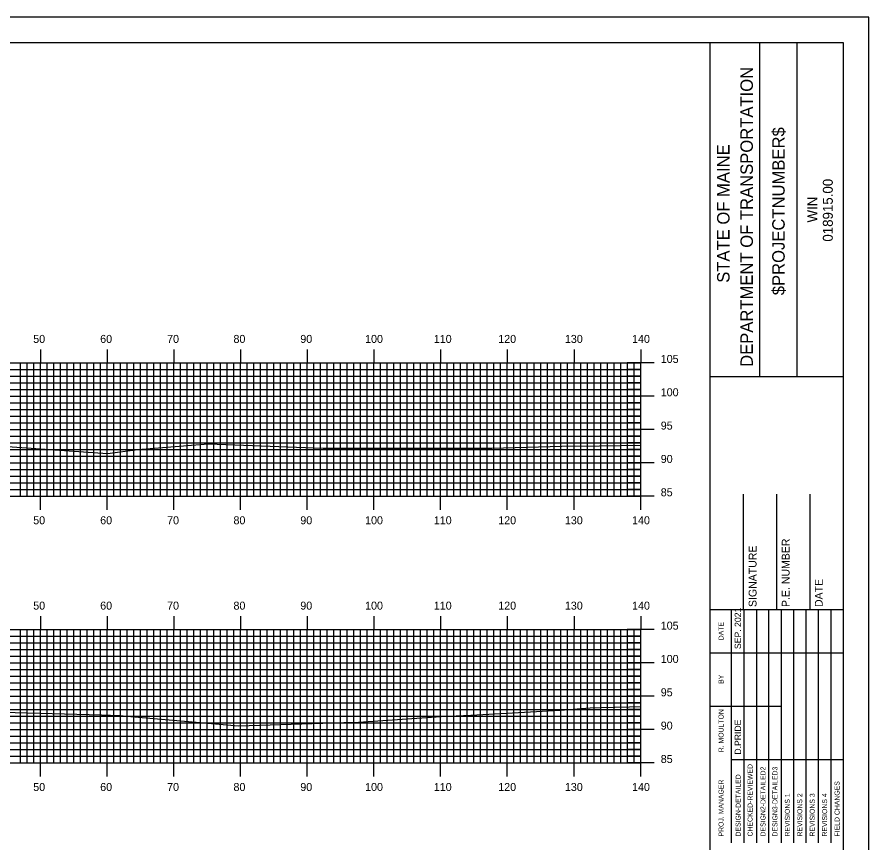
# Model space of a CAD drawing. Extents: x 1763759 to 1764102, y 442591 to 442811.
# Drawn here: x 1763970.8 to 1764098.5, y 442686.7 to 442810.5 of the extents above; entities that cross this region are included whole.
import ezdxf

# ---------------------------------------------------------------- set-up
doc = ezdxf.new("R2010")
doc.units = 0
for name, color, linetype in [('BORDER', 7, 'Continuous'), ('H_V ANNOTATION', 7, 'Continuous'), ('MAJOR', 7, 'Continuous'), ('MINOR', 7, 'Continuous'), ('PLOT BOUNDARY', 7, 'Continuous'), ('S_Roadway_Centerline', 7, 'Continuous')]:
    doc.layers.add(name, color=color, linetype=linetype)

msp = doc.modelspace()

# ---------------------------------------------------------------- linework, layer by layer
at = {"layer": 'BORDER'}
for p, q in [((1764074.72, 442596.67), (1764074.72, 442806.67)), ((1764082.18, 442756.66), (1764082.18, 442806.66)), ((1764087.77, 442756.66), (1764087.77, 442806.66)), ((1764074.72, 442756.65), (1764094.72, 442756.65)), ((1764079.72, 442721.67), (1764079.72, 442738.97)), ((1764084.72, 442721.67), (1764084.72, 442738.97)), ((1764089.72, 442721.67), (1764089.72, 442738.97)), ((1764074.72, 442721.67), (1764094.72, 442721.67))]:
    msp.add_line(p, q, dxfattribs=at)
msp.add_lwpolyline([(1763774.72, 442596.67), (1764094.72, 442596.67), (1764094.72, 442806.67), (1763774.72, 442806.67)], close=True, dxfattribs=at)
for points in [[(1764077.95, 442715.17), (1764077.95, 442721.67)], [(1764079.81, 442686.68), (1764079.81, 442721.67)], [(1764081.68, 442721.67), (1764081.68, 442686.68)], [(1764083.54, 442686.68), (1764083.54, 442721.67)], [(1764085.4, 442686.68), (1764085.4, 442721.67)], [(1764087.27, 442686.68), (1764087.27, 442721.67)], [(1764089.13, 442686.68), (1764089.13, 442721.67)], [(1764090.99, 442686.68), (1764090.99, 442721.67)], [(1764092.86, 442686.68), (1764092.86, 442721.67)], [(1764077.95, 442686.68), (1764077.95, 442720.26)], [(1764074.72, 442715.17), (1764094.72, 442715.17)], [(1764074.72, 442707.17), (1764077.95, 442707.17)], [(1764077.95, 442707.17), (1764085.4, 442707.17)], [(1764077.95, 442699.17), (1764094.72, 442699.17)]]:
    msp.add_lwpolyline(points, dxfattribs=at)
at = {"layer": 'MAJOR'}
for p, q in [((1763974.32, 442760.67), (1763974.32, 442758.67)), ((1763984.32, 442760.67), (1763984.32, 442758.67)), ((1763994.32, 442760.67), (1763994.32, 442758.67)), ((1764004.32, 442760.67), (1764004.32, 442758.67)), ((1764014.32, 442760.67), (1764014.32, 442758.67)), ((1764024.32, 442760.67), (1764024.32, 442758.67)), ((1764034.32, 442760.67), (1764034.32, 442758.67)), ((1764044.32, 442760.67), (1764044.32, 442758.67)), ((1764054.32, 442760.67), (1764054.32, 442758.67)), ((1764064.32, 442760.67), (1764064.32, 442758.67)), ((1763784.32, 442758.67), (1764064.32, 442758.67)), ((1763784.32, 442758.67), (1764064.32, 442758.67)), ((1763974.32, 442738.67), (1763974.32, 442758.67)), ((1763984.32, 442738.67), (1763984.32, 442758.67)), ((1763994.32, 442738.67), (1763994.32, 442758.67)), ((1764004.32, 442738.67), (1764004.32, 442758.67)), ((1764014.32, 442738.67), (1764014.32, 442758.67)), ((1764024.32, 442738.67), (1764024.32, 442758.67)), ((1764034.32, 442738.67), (1764034.32, 442758.67)), ((1764044.32, 442738.67), (1764044.32, 442758.67)), ((1764054.32, 442738.67), (1764054.32, 442758.67)), ((1764066.32, 442758.67), (1764062.31, 442758.67)), ((1764064.32, 442738.67), (1764064.32, 442758.67)), ((1764064.32, 442738.67), (1764064.32, 442758.67)), ((1763784.32, 442753.67), (1764064.32, 442753.67)), ((1764066.32, 442753.67), (1764062.31, 442753.67)), ((1763784.32, 442748.67), (1764064.32, 442748.67)), ((1764066.32, 442748.67), (1764062.31, 442748.67)), ((1763784.32, 442743.67), (1764064.32, 442743.67)), ((1764066.32, 442743.67), (1764062.31, 442743.67)), ((1763784.32, 442738.67), (1764064.32, 442738.67)), ((1763784.32, 442738.67), (1764064.32, 442738.67)), ((1763974.32, 442736.66), (1763974.32, 442738.67)), ((1763984.32, 442736.66), (1763984.32, 442738.67)), ((1763994.32, 442736.66), (1763994.32, 442738.67)), ((1764004.32, 442736.66), (1764004.32, 442738.67)), ((1764014.32, 442736.66), (1764014.32, 442738.67)), ((1764024.32, 442736.66), (1764024.32, 442738.67)), ((1764034.32, 442736.66), (1764034.32, 442738.67)), ((1764044.32, 442736.66), (1764044.32, 442738.67)), ((1764054.32, 442736.66), (1764054.32, 442738.67)), ((1764066.32, 442738.67), (1764062.31, 442738.67)), ((1764064.32, 442736.66), (1764064.32, 442738.67)), ((1763974.32, 442720.67), (1763974.32, 442718.67)), ((1763984.32, 442720.67), (1763984.32, 442718.67)), ((1763994.32, 442720.67), (1763994.32, 442718.67)), ((1764004.32, 442720.67), (1764004.32, 442718.67)), ((1764014.32, 442720.67), (1764014.32, 442718.67)), ((1764024.32, 442720.67), (1764024.32, 442718.67)), ((1764034.32, 442720.67), (1764034.32, 442718.67)), ((1764044.32, 442720.67), (1764044.32, 442718.67)), ((1764054.32, 442720.67), (1764054.32, 442718.67)), ((1764064.32, 442720.67), (1764064.32, 442718.67)), ((1763784.32, 442718.67), (1764064.32, 442718.67)), ((1763784.32, 442718.67), (1764064.32, 442718.67)), ((1763974.32, 442698.67), (1763974.32, 442718.67)), ((1763984.32, 442698.67), (1763984.32, 442718.67)), ((1763994.32, 442698.67), (1763994.32, 442718.67)), ((1764004.32, 442698.67), (1764004.32, 442718.67)), ((1764014.32, 442698.67), (1764014.32, 442718.67)), ((1764024.32, 442698.67), (1764024.32, 442718.67)), ((1764034.32, 442698.67), (1764034.32, 442718.67)), ((1764044.32, 442698.67), (1764044.32, 442718.67)), ((1764054.32, 442698.67), (1764054.32, 442718.67)), ((1764066.32, 442718.67), (1764062.31, 442718.67)), ((1764064.32, 442698.67), (1764064.32, 442718.67)), ((1764064.32, 442698.67), (1764064.32, 442718.67)), ((1763784.32, 442713.67), (1764064.32, 442713.67)), ((1764066.32, 442713.67), (1764062.31, 442713.67)), ((1763784.32, 442708.67), (1764064.32, 442708.67)), ((1764066.32, 442708.67), (1764062.31, 442708.67)), ((1763784.32, 442703.67), (1764064.32, 442703.67)), ((1764066.32, 442703.67), (1764062.31, 442703.67)), ((1763784.32, 442698.67), (1764064.32, 442698.67)), ((1763784.32, 442698.67), (1764064.32, 442698.67)), ((1763974.32, 442696.66), (1763974.32, 442698.67)), ((1763984.32, 442696.66), (1763984.32, 442698.67)), ((1763994.32, 442696.66), (1763994.32, 442698.67)), ((1764004.32, 442696.66), (1764004.32, 442698.67)), ((1764014.32, 442696.66), (1764014.32, 442698.67)), ((1764024.32, 442696.66), (1764024.32, 442698.67)), ((1764034.32, 442696.66), (1764034.32, 442698.67)), ((1764044.32, 442696.66), (1764044.32, 442698.67)), ((1764054.32, 442696.66), (1764054.32, 442698.67)), ((1764066.32, 442698.67), (1764062.31, 442698.67)), ((1764064.32, 442696.66), (1764064.32, 442698.67))]:
    msp.add_line(p, q, dxfattribs=at)
at = {"layer": 'MINOR'}
for p, q in [((1763971.32, 442738.67), (1763971.32, 442758.67)), ((1763972.32, 442738.67), (1763972.32, 442758.67)), ((1763973.32, 442738.67), (1763973.32, 442758.67)), ((1763975.32, 442738.67), (1763975.32, 442758.67)), ((1763976.32, 442738.67), (1763976.32, 442758.67)), ((1763977.32, 442738.67), (1763977.32, 442758.67)), ((1763978.32, 442738.67), (1763978.32, 442758.67)), ((1763979.32, 442738.67), (1763979.32, 442758.67)), ((1763980.32, 442738.67), (1763980.32, 442758.67)), ((1763981.32, 442738.67), (1763981.32, 442758.67)), ((1763982.32, 442738.67), (1763982.32, 442758.67)), ((1763983.32, 442738.67), (1763983.32, 442758.67)), ((1763985.32, 442738.67), (1763985.32, 442758.67)), ((1763986.32, 442738.67), (1763986.32, 442758.67)), ((1763987.32, 442738.67), (1763987.32, 442758.67)), ((1763988.32, 442738.67), (1763988.32, 442758.67)), ((1763989.32, 442738.67), (1763989.32, 442758.67)), ((1763990.32, 442738.67), (1763990.32, 442758.67)), ((1763991.32, 442738.67), (1763991.32, 442758.67)), ((1763992.32, 442738.67), (1763992.32, 442758.67)), ((1763993.32, 442738.67), (1763993.32, 442758.67)), ((1763995.32, 442738.67), (1763995.32, 442758.67)), ((1763996.32, 442738.67), (1763996.32, 442758.67)), ((1763997.32, 442738.67), (1763997.32, 442758.67)), ((1763998.32, 442738.67), (1763998.32, 442758.67)), ((1763999.32, 442738.67), (1763999.32, 442758.67)), ((1764000.32, 442738.67), (1764000.32, 442758.67)), ((1764001.32, 442738.67), (1764001.32, 442758.67)), ((1764002.32, 442738.67), (1764002.32, 442758.67)), ((1764003.32, 442738.67), (1764003.32, 442758.67)), ((1764005.32, 442738.67), (1764005.32, 442758.67)), ((1764006.32, 442738.67), (1764006.32, 442758.67)), ((1764007.32, 442738.67), (1764007.32, 442758.67)), ((1764008.32, 442738.67), (1764008.32, 442758.67)), ((1764009.32, 442738.67), (1764009.32, 442758.67)), ((1764010.32, 442738.67), (1764010.32, 442758.67)), ((1764011.32, 442738.67), (1764011.32, 442758.67)), ((1764012.32, 442738.67), (1764012.32, 442758.67)), ((1764013.32, 442738.67), (1764013.32, 442758.67)), ((1764015.32, 442738.67), (1764015.32, 442758.67)), ((1764016.32, 442738.67), (1764016.32, 442758.67)), ((1764017.32, 442738.67), (1764017.32, 442758.67)), ((1764018.32, 442738.67), (1764018.32, 442758.67)), ((1764019.32, 442738.67), (1764019.32, 442758.67)), ((1764020.32, 442738.67), (1764020.32, 442758.67)), ((1764021.32, 442738.67), (1764021.32, 442758.67)), ((1764022.32, 442738.67), (1764022.32, 442758.67)), ((1764023.32, 442738.67), (1764023.32, 442758.67)), ((1764025.32, 442738.67), (1764025.32, 442758.67)), ((1764026.32, 442738.67), (1764026.32, 442758.67)), ((1764027.32, 442738.67), (1764027.32, 442758.67)), ((1764028.32, 442738.67), (1764028.32, 442758.67)), ((1764029.32, 442738.67), (1764029.32, 442758.67)), ((1764030.32, 442738.67), (1764030.32, 442758.67)), ((1764031.32, 442738.67), (1764031.32, 442758.67)), ((1764032.32, 442738.67), (1764032.32, 442758.67)), ((1764033.32, 442738.67), (1764033.32, 442758.67)), ((1764035.32, 442738.67), (1764035.32, 442758.67)), ((1764036.32, 442738.67), (1764036.32, 442758.67)), ((1764037.32, 442738.67), (1764037.32, 442758.67)), ((1764038.32, 442738.67), (1764038.32, 442758.67)), ((1764039.32, 442738.67), (1764039.32, 442758.67)), ((1764040.32, 442738.67), (1764040.32, 442758.67)), ((1764041.32, 442738.67), (1764041.32, 442758.67)), ((1764042.32, 442738.67), (1764042.32, 442758.67)), ((1764043.32, 442738.67), (1764043.32, 442758.67)), ((1764045.32, 442738.67), (1764045.32, 442758.67)), ((1764046.32, 442738.67), (1764046.32, 442758.67)), ((1764047.32, 442738.67), (1764047.32, 442758.67)), ((1764048.32, 442738.67), (1764048.32, 442758.67)), ((1764049.32, 442738.67), (1764049.32, 442758.67)), ((1764050.32, 442738.67), (1764050.32, 442758.67)), ((1764051.32, 442738.67), (1764051.32, 442758.67)), ((1764052.32, 442738.67), (1764052.32, 442758.67)), ((1764053.32, 442738.67), (1764053.32, 442758.67)), ((1764055.32, 442738.67), (1764055.32, 442758.67)), ((1764056.32, 442738.67), (1764056.32, 442758.67)), ((1764057.32, 442738.67), (1764057.32, 442758.67)), ((1764058.32, 442738.67), (1764058.32, 442758.67)), ((1764059.32, 442738.67), (1764059.32, 442758.67)), ((1764060.32, 442738.67), (1764060.32, 442758.67)), ((1764061.32, 442738.67), (1764061.32, 442758.67)), ((1764062.32, 442738.67), (1764062.32, 442758.67)), ((1764063.32, 442738.67), (1764063.32, 442758.67)), ((1763784.32, 442757.67), (1764064.32, 442757.67)), ((1764064.32, 442757.67), (1764062.31, 442757.67)), ((1763784.32, 442756.67), (1764064.32, 442756.67)), ((1764064.32, 442756.67), (1764062.31, 442756.67)), ((1763784.32, 442755.67), (1764064.32, 442755.67)), ((1763784.32, 442754.67), (1764064.32, 442754.67)), ((1764064.32, 442755.67), (1764062.31, 442755.67)), ((1764064.32, 442754.67), (1764062.31, 442754.67)), ((1763784.32, 442752.67), (1764064.32, 442752.67)), ((1764064.32, 442752.67), (1764062.31, 442752.67)), ((1763784.32, 442751.67), (1764064.32, 442751.67)), ((1764064.32, 442751.67), (1764062.31, 442751.67)), ((1763784.32, 442750.67), (1764064.32, 442750.67)), ((1763784.32, 442749.67), (1764064.32, 442749.67)), ((1764064.32, 442750.67), (1764062.31, 442750.67)), ((1764064.32, 442749.67), (1764062.31, 442749.67)), ((1763784.32, 442747.67), (1764064.32, 442747.67)), ((1764064.32, 442747.67), (1764062.31, 442747.67)), ((1763784.32, 442746.67), (1764064.32, 442746.67)), ((1764064.32, 442746.67), (1764062.31, 442746.67)), ((1763784.32, 442745.67), (1764064.32, 442745.67)), ((1763784.32, 442744.67), (1764064.32, 442744.67)), ((1764064.32, 442745.67), (1764062.31, 442745.67)), ((1764064.32, 442744.67), (1764062.31, 442744.67)), ((1763784.32, 442742.67), (1764064.32, 442742.67)), ((1764064.32, 442742.67), (1764062.31, 442742.67)), ((1763784.32, 442741.67), (1764064.32, 442741.67)), ((1763784.32, 442740.67), (1764064.32, 442740.67)), ((1764064.32, 442741.67), (1764062.31, 442741.67)), ((1764064.32, 442740.67), (1764062.31, 442740.67)), ((1763784.32, 442739.67), (1764064.32, 442739.67)), ((1764064.32, 442739.67), (1764062.31, 442739.67)), ((1763784.32, 442717.67), (1764064.32, 442717.67)), ((1763971.32, 442698.67), (1763971.32, 442718.67)), ((1763972.32, 442698.67), (1763972.32, 442718.67)), ((1763973.32, 442698.67), (1763973.32, 442718.67)), ((1763975.32, 442698.67), (1763975.32, 442718.67)), ((1763976.32, 442698.67), (1763976.32, 442718.67)), ((1763977.32, 442698.67), (1763977.32, 442718.67)), ((1763978.32, 442698.67), (1763978.32, 442718.67)), ((1763979.32, 442698.67), (1763979.32, 442718.67)), ((1763980.32, 442698.67), (1763980.32, 442718.67)), ((1763981.32, 442698.67), (1763981.32, 442718.67)), ((1763982.32, 442698.67), (1763982.32, 442718.67)), ((1763983.32, 442698.67), (1763983.32, 442718.67)), ((1763985.32, 442698.67), (1763985.32, 442718.67)), ((1763986.32, 442698.67), (1763986.32, 442718.67)), ((1763987.32, 442698.67), (1763987.32, 442718.67)), ((1763988.32, 442698.67), (1763988.32, 442718.67)), ((1763989.32, 442698.67), (1763989.32, 442718.67)), ((1763990.32, 442698.67), (1763990.32, 442718.67)), ((1763991.32, 442698.67), (1763991.32, 442718.67)), ((1763992.32, 442698.67), (1763992.32, 442718.67)), ((1763993.32, 442698.67), (1763993.32, 442718.67)), ((1763995.32, 442698.67), (1763995.32, 442718.67)), ((1763996.32, 442698.67), (1763996.32, 442718.67)), ((1763997.32, 442698.67), (1763997.32, 442718.67)), ((1763998.32, 442698.67), (1763998.32, 442718.67)), ((1763999.32, 442698.67), (1763999.32, 442718.67)), ((1764000.32, 442698.67), (1764000.32, 442718.67)), ((1764001.32, 442698.67), (1764001.32, 442718.67)), ((1764002.32, 442698.67), (1764002.32, 442718.67)), ((1764003.32, 442698.67), (1764003.32, 442718.67)), ((1764005.32, 442698.67), (1764005.32, 442718.67)), ((1764006.32, 442698.67), (1764006.32, 442718.67)), ((1764007.32, 442698.67), (1764007.32, 442718.67)), ((1764008.32, 442698.67), (1764008.32, 442718.67)), ((1764009.32, 442698.67), (1764009.32, 442718.67)), ((1764010.32, 442698.67), (1764010.32, 442718.67)), ((1764011.32, 442698.67), (1764011.32, 442718.67)), ((1764012.32, 442698.67), (1764012.32, 442718.67)), ((1764013.32, 442698.67), (1764013.32, 442718.67)), ((1764015.32, 442698.67), (1764015.32, 442718.67)), ((1764016.32, 442698.67), (1764016.32, 442718.67)), ((1764017.32, 442698.67), (1764017.32, 442718.67)), ((1764018.32, 442698.67), (1764018.32, 442718.67)), ((1764019.32, 442698.67), (1764019.32, 442718.67)), ((1764020.32, 442698.67), (1764020.32, 442718.67)), ((1764021.32, 442698.67), (1764021.32, 442718.67)), ((1764022.32, 442698.67), (1764022.32, 442718.67)), ((1764023.32, 442698.67), (1764023.32, 442718.67)), ((1764025.32, 442698.67), (1764025.32, 442718.67)), ((1764026.32, 442698.67), (1764026.32, 442718.67)), ((1764027.32, 442698.67), (1764027.32, 442718.67)), ((1764028.32, 442698.67), (1764028.32, 442718.67)), ((1764029.32, 442698.67), (1764029.32, 442718.67)), ((1764030.32, 442698.67), (1764030.32, 442718.67)), ((1764031.32, 442698.67), (1764031.32, 442718.67)), ((1764032.32, 442698.67), (1764032.32, 442718.67)), ((1764033.32, 442698.67), (1764033.32, 442718.67)), ((1764035.32, 442698.67), (1764035.32, 442718.67)), ((1764036.32, 442698.67), (1764036.32, 442718.67)), ((1764037.32, 442698.67), (1764037.32, 442718.67)), ((1764038.32, 442698.67), (1764038.32, 442718.67)), ((1764039.32, 442698.67), (1764039.32, 442718.67)), ((1764040.32, 442698.67), (1764040.32, 442718.67)), ((1764041.32, 442698.67), (1764041.32, 442718.67)), ((1764042.32, 442698.67), (1764042.32, 442718.67)), ((1764043.32, 442698.67), (1764043.32, 442718.67)), ((1764045.32, 442698.67), (1764045.32, 442718.67)), ((1764046.32, 442698.67), (1764046.32, 442718.67)), ((1764047.32, 442698.67), (1764047.32, 442718.67)), ((1764048.32, 442698.67), (1764048.32, 442718.67)), ((1764049.32, 442698.67), (1764049.32, 442718.67)), ((1764050.32, 442698.67), (1764050.32, 442718.67)), ((1764051.32, 442698.67), (1764051.32, 442718.67)), ((1764052.32, 442698.67), (1764052.32, 442718.67)), ((1764053.32, 442698.67), (1764053.32, 442718.67)), ((1764055.32, 442698.67), (1764055.32, 442718.67)), ((1764056.32, 442698.67), (1764056.32, 442718.67)), ((1764057.32, 442698.67), (1764057.32, 442718.67)), ((1764058.32, 442698.67), (1764058.32, 442718.67)), ((1764059.32, 442698.67), (1764059.32, 442718.67)), ((1764060.32, 442698.67), (1764060.32, 442718.67)), ((1764061.32, 442698.67), (1764061.32, 442718.67)), ((1764064.32, 442717.67), (1764062.31, 442717.67)), ((1764062.32, 442698.67), (1764062.32, 442718.67)), ((1764063.32, 442698.67), (1764063.32, 442718.67)), ((1763784.32, 442716.67), (1764064.32, 442716.67)), ((1764064.32, 442716.67), (1764062.31, 442716.67)), ((1763784.32, 442715.67), (1764064.32, 442715.67)), ((1764064.32, 442715.67), (1764062.31, 442715.67)), ((1763784.32, 442714.67), (1764064.32, 442714.67)), ((1764064.32, 442714.67), (1764062.31, 442714.67)), ((1763784.32, 442712.67), (1764064.32, 442712.67)), ((1764064.32, 442712.67), (1764062.31, 442712.67)), ((1763784.32, 442711.67), (1764064.32, 442711.67)), ((1764064.32, 442711.67), (1764062.31, 442711.67)), ((1763784.32, 442710.67), (1764064.32, 442710.67)), ((1764064.32, 442710.67), (1764062.31, 442710.67)), ((1763784.32, 442709.67), (1764064.32, 442709.67)), ((1764064.32, 442709.67), (1764062.31, 442709.67)), ((1763784.32, 442707.67), (1764064.32, 442707.67)), ((1764064.32, 442707.67), (1764062.31, 442707.67)), ((1763784.32, 442706.67), (1764064.32, 442706.67)), ((1764064.32, 442706.67), (1764062.31, 442706.67)), ((1763784.32, 442705.67), (1764064.32, 442705.67)), ((1764064.32, 442705.67), (1764062.31, 442705.67)), ((1763784.32, 442704.67), (1764064.32, 442704.67)), ((1764064.32, 442704.67), (1764062.31, 442704.67)), ((1763784.32, 442702.67), (1764064.32, 442702.67)), ((1764064.32, 442702.67), (1764062.31, 442702.67)), ((1763784.32, 442701.67), (1764064.32, 442701.67)), ((1764064.32, 442701.67), (1764062.31, 442701.67)), ((1763784.32, 442700.67), (1764064.32, 442700.67)), ((1764064.32, 442700.67), (1764062.31, 442700.67)), ((1763784.32, 442699.67), (1764064.32, 442699.67)), ((1764064.32, 442699.67), (1764062.31, 442699.67))]:
    msp.add_line(p, q, dxfattribs=at)
at = {"layer": 'PLOT BOUNDARY'}
msp.add_lwpolyline([(1763758.53, 442590.55), (1764098.53, 442590.55), (1764098.53, 442810.55), (1763758.53, 442810.55)], close=True, dxfattribs=at)
at = {"layer": 'S_Roadway_Centerline'}
for points in [[(1763967.27, 442746.28), (1763975.06, 442745.73), (1763984.41, 442745.09), (1763988.91, 442745.67), (1763999.48, 442746.56), (1764016.71, 442745.91), (1764017.03, 442745.9), (1764017.3, 442745.91), (1764034.83, 442745.87), (1764042.01, 442745.91), (1764052.51, 442746.2), (1764058.13, 442746.24), (1764064.32, 442746.32)], [(1763966.79, 442706.36), (1763983.49, 442705.89), (1763986.17, 442705.81), (1763990.72, 442705.4), (1764004.01, 442704.22), (1764019.79, 442704.72), (1764020.94, 442704.75), (1764021.23, 442704.76), (1764022.03, 442704.79), (1764034.42, 442705.63), (1764038.84, 442705.86), (1764052.23, 442706.61), (1764056.76, 442706.93), (1764058.26, 442706.99), (1764062.64, 442707.08), (1764064.32, 442707.12)]]:
    msp.add_lwpolyline(points, dxfattribs=at)

# ---------------------------------------------------------------- texts
at = {"layer": 'BORDER'}
for s, height, p in [('DEPARTMENT OF TRANSPORTATION', 1.8635, (1764081.13, 442758.08)), ('$PROJECTNUMBER$', 1.8635, (1764085.9, 442768.82)), ('STATE OF MAINE', 1.8635, (1764077.63, 442770.69)), ('018915.00', 1.491, (1764093.11, 442776.86)), ('WIN', 1.491, (1764090.79, 442779.73)), ('P.E. NUMBER', 1.1811, (1764086.64, 442722.06)), ('SIGNATURE', 1.181, (1764081.68, 442722.06)), ('DATE', 1.181, (1764091.6, 442722.06)), ('SEP. 2021', 0.969, (1764079.36, 442715.76)), ('DATE', 0.743, (1764076.73, 442717.08)), ('BY', 0.743, (1764076.73, 442710.54)), ('R. MOULTON', 0.745, (1764076.73, 442700.28)), ('D.PRIDE', 0.969, (1764079.36, 442699.92)), ('CHECKED-REVIEWED', 0.7455, (1764081.08, 442687.65)), ('DESIGN2-DETAILED2', 0.7455, (1764083.02, 442687.65)), ('DESIGN3-DETAILED3', 0.7455, (1764084.81, 442687.65)), ('DESIGN-DETAILED', 0.7455, (1764079.29, 442687.65)), ('PROJ. MANAGER', 0.7455, (1764076.73, 442687.65)), ('FIELD CHANGES', 0.7455, (1764094.12, 442687.65)), ('REVISIONS 1', 0.7455, (1764086.67, 442687.65)), ('REVISIONS 2', 0.7455, (1764088.53, 442687.65)), ('REVISIONS 3', 0.7455, (1764090.4, 442687.65)), ('REVISIONS 4', 0.7455, (1764092.26, 442687.65))]:
    msp.add_text(s, height=height, rotation=90, dxfattribs=at).set_placement(p)
at = {"layer": 'H_V ANNOTATION'}
for s, p in [('50', (1763973.25, 442761.67)), ('60', (1763983.29, 442761.67)), ('70', (1763993.32, 442761.67)), ('80', (1764003.27, 442761.67)), ('90', (1764013.29, 442761.67)), ('100', (1764023, 442761.67)), ('110', (1764033.3, 442761.67)), ('120', (1764042.96, 442761.67)), ('130', (1764052.95, 442761.67)), ('140', (1764063.02, 442761.67)), ('105', (1764067.32, 442758.67)), ('100', (1764067.32, 442753.67)), ('95', (1764067.32, 442748.67)), ('90', (1764067.32, 442743.67)), ('85', (1764067.32, 442738.67)), ('50', (1763973.25, 442734.47)), ('60', (1763983.29, 442734.47)), ('70', (1763993.32, 442734.47)), ('80', (1764003.27, 442734.47)), ('90', (1764013.29, 442734.47)), ('100', (1764023, 442734.47)), ('110', (1764033.3, 442734.47)), ('120', (1764042.96, 442734.47)), ('130', (1764052.95, 442734.47)), ('140', (1764063.02, 442734.47)), ('50', (1763973.25, 442721.67)), ('60', (1763983.29, 442721.67)), ('70', (1763993.32, 442721.67)), ('80', (1764003.27, 442721.67)), ('90', (1764013.29, 442721.67)), ('100', (1764023, 442721.67)), ('110', (1764033.3, 442721.67)), ('120', (1764042.96, 442721.67)), ('130', (1764052.95, 442721.67)), ('140', (1764063.02, 442721.67)), ('105', (1764067.32, 442718.67)), ('100', (1764067.32, 442713.67)), ('95', (1764067.32, 442708.67)), ('90', (1764067.32, 442703.67)), ('85', (1764067.32, 442698.67)), ('50', (1763973.25, 442694.47)), ('60', (1763983.29, 442694.47)), ('70', (1763993.32, 442694.47)), ('80', (1764003.27, 442694.47)), ('90', (1764013.29, 442694.47)), ('100', (1764023, 442694.47)), ('110', (1764033.3, 442694.47)), ('120', (1764042.96, 442694.47)), ('130', (1764052.95, 442694.47)), ('140', (1764063.02, 442694.47))]:
    msp.add_text(s, height=1.2, dxfattribs=at).set_placement(p)

doc.saveas('drawing.dxf')
